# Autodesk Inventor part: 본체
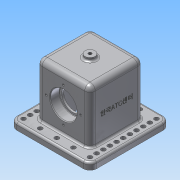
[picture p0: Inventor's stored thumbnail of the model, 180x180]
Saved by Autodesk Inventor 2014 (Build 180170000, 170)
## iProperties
Created: 2018-11
Part Number: 본체
Material: 알루미늄 6061
Document SubType Name: Modeling
Designer: Administrator
Density: 2.71 g/cm^3
Appearance: 알루미늄 - 평지
Mass: 1020.47 g
Surface Area: 775.884 cm^2
Volume: 376.558 cm^3
Author: Administrator
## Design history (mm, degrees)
sketch "스케치1"
  geometry: L1 (-60, -60)-(60, -60); L2 (60, -60)-(60, 60); L3 (60, 60)-(-60, 60); L4 (-60, 60)-(-60, -60); L5 (-60, -60)-(60, 60); L6 (60, -60)-(-60, 60); 1 further point
  constraints: 12 end point, 2 midpoint, 2 parallel, 1 horizontal, 1 perpendicular
  dimensions: "d0" = 120 distance of L3.end L2.end; "d1" = 120 distance of L2.end L1.end
extrude "돌출1" new body sketch "스케치1" distance "d2" = 10; taper "d3" = 0 deg
sketch "스케치2"
  geometry: L1 (-40, -40)-(40, -40); L2 (40, -40)-(40, 40); L3 (40, 40)-(-40, 40); L4 (-40, 40)-(-40, -40); L5 (-40, -40)-(40, 40); L6 (40, -40)-(-40, 40); 1 further point
  constraints: 12 end point, 2 midpoint, 2 parallel, 1 horizontal, 1 perpendicular
  dimensions: "d4" = 80 distance of L3.end L2.end; "d5" = 80 distance of L2.end L1.end
extrude "돌출2" join sketch "스케치2" distance "d6" = 80; taper "d7" = 0 deg
sketch "스케치4"
  geometry: C1 r 7.5 at (0, 0); 1 further point
  constraints: 1 centre point, 1 coincident
  dimensions: "d10" = 15 diameter of C1
extrude "돌출3" join sketch "스케치4" distance "d11" = 5; taper "d12" = 0 deg
node "작업 평면3"
sketch "스케치7"
  geometry: L1 (-60, 0)-(-60, 10) reference; L2 (-60, 10)-(-40, 10) reference; L3 (-40, 10)-(-40, 90) reference; L4 (-40, 90)-(-7.5, 90) reference; L5 (-7.5, 90)-(-7.5, 95) reference; L6 (-7.5, 95)-(7.5, 95) reference; L7 (7.5, 95)-(7.5, 90) reference; L8 (7.5, 90)-(40, 90) reference; L9 (40, 90)-(40, 10) reference; L10 (40, 10)-(60, 10) reference; L11 (60, 10)-(60, 0) reference; L12 (60, 0)-(-60, 0) reference; L13 (0, 0)-(0, 48); L14 (0, 48)-(-40, 48); L15 (-40, 48)-(-40, 68); L16 (-40, 68)-(-26, 68); L17 (-26, 68)-(-26, 64.5); L18 (-26, 64.5)-(-23, 64.5); L19 (-23, 64.5)-(-23, 48); L20 (23, 64.5)-(23, 48); L21 (26, 64.5)-(23, 64.5); L22 (26, 68)-(26, 64.5); L23 (40, 68)-(26, 68); L24 (40, 48)-(40, 68); L25 (0, 48)-(40, 48)
  constraints: 26 end point, 6 symmetric about line, 5 perpendicular, 4 point on line, 1 parallel
  dimensions: "d28" = 48 distance of L13.start L13.end; "d29" = 14 distance of L15.end L16.end; "d30" = 3 distance of L17.end L18.end; "d31" = 40 diameter of L16 L14; "d32" = 33 diameter of L18 L14
revolve "회전1" sketch "스케치7" stored, may be unused: angle "d33" = 90 deg
sketch "스케치8"
  geometry: L1 (30, -23)-(-30, -23); L2 (-30, -23)-(-30, 23); L3 (-30, 23)-(30, 23); L4 (30, 23)-(30, -23); L5 (30, -23)-(-30, 23); L6 (-30, -23)-(30, 23); 1 further point
  constraints: 12 end point, 2 midpoint, 2 parallel, 1 horizontal, 1 perpendicular
  dimensions: "d34" = 60 distance of L2.end L3.end; "d35" = 46 distance of L1.end L2.end
extrude "돌출4" cut sketch "스케치8" distance "d36" = 80; taper "d37" = 0 deg
sketch "스케치9" dims "d38" = 52
  geometry: L1 (100, 0)-(100, -10) reference; L2 (100, -10)-(-20, -10) reference; L3 (-20, -10)-(-20, 0) reference; L4 (-20, 0)-(0, 0) reference; L5 (0, 0)-(80, 0) reference; L6 (80, 0)-(100, 0) reference; L7 (0, 0)-(0, 80) reference; L8 (0, 80)-(80, 80) reference; L9 (80, 80)-(80, 0) reference; C1 r 20 at (40, 38) reference; C2 r 20 at (40, 38) reference; 3 further points
  constraints: 2 horizontal alignment, 1 coincident, 2 other
hole "구멍1" sketch "스케치9" at (66, 38) diameter "d39" = 3.242; stored, may be unused: countersink angle "d43" = 90 deg, drill point angle "d45" = 118 deg; dims "d40" = 8, "d41" = 4, "d42" = 2, "d44" = 10
hole "구멍2" diameter "d51" = 4.917; stored, may be unused: countersink angle "d55" = 90 deg, drill point angle "d57" = 0 deg; dims "d49" = 10, "d50" = 10, "d52" = 8, "d53" = 4, "d54" = 2, "d56" = 10
fillet "모깎기1" dims "d58" = 3
chamfer "모따기1" distance "d59" = 1; stored, may be unused: second distance "d60" = 2, angle "d61" = 45 deg
fillet "모깎기2" dims "d62" = 10
sketch "스케치10"
  geometry: A1 r 10 centre (-50, 50) between (-50, 60) and (-60, 50) reference; 2 further points
  constraints: 1 coincident
hole "구멍3" sketch "스케치10" at (-50, 50) diameter "d63" = 6.6; stored, may be unused: countersink angle "d67" = 90 deg, drill point angle "d69" = 0 deg; dims "d64" = 8, "d65" = 4, "d66" = 2, "d68" = 10
fillet "모깎기3" dims "d76" = 8
fillet "모깎기4" dims "d77" = 8
sketch "스케치13"
  geometry: L1 (10, -18)-(10, 82) reference; L2 (-85, 39.5)-(-85, 24.5) reference; 3 further points
  constraints: 1 horizontal alignment, 1 midpoint, 1 other
  dimensions: "d80" = 48 distance from line of L1 point (-38, 32)
feature "엠보싱1" sketch "스케치13" dims "d0" = 120, "d1" = 120, "d81" = 0.5, "d82" = 0
fillet "모깎기5" dims "d83" = 3
fillet "모깎기6" dims "d84" = 3
fillet "모깎기7" dims "d85" = 3
fillet "모깎기8" dims "d86" = 0.6
fillet "모깎기9" dims "d93" = 3
chamfer "모따기2" distance "d94" = 1; stored, may be unused: second distance "d95" = 2, angle "d96" = 45 deg
node "솔리드1"
pattern_circular "원형 패턴1" dims angle "d47" = 360 deg
mirror "대칭1"
mirror "대칭2"
mirror "대칭3"
pattern_linear "직사각형 패턴3" dims "d89" = 10
pattern_linear "직사각형 패턴4" dims "d92" = 25
mirror "대칭4"
mirror "대칭5"
node "절단 모서리 투영3"
node "절단 모서리 투영4"
other parameters: "d13" = 0
